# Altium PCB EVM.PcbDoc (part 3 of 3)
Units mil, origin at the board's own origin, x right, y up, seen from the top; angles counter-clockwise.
Board outline 4950 x 3450 mil, 6 copper layers (Top Layer, Power Layer 1 (PWR), Power Layer 2 (GND), Power Layer 3 (PWR), Power Layer 4 (GND), Bottom Layer), stack 58.4 mil thick; 378 components, 191 nets, 2749 pads, 0 vias.
Unrouted connection lines stored in the file: 482.
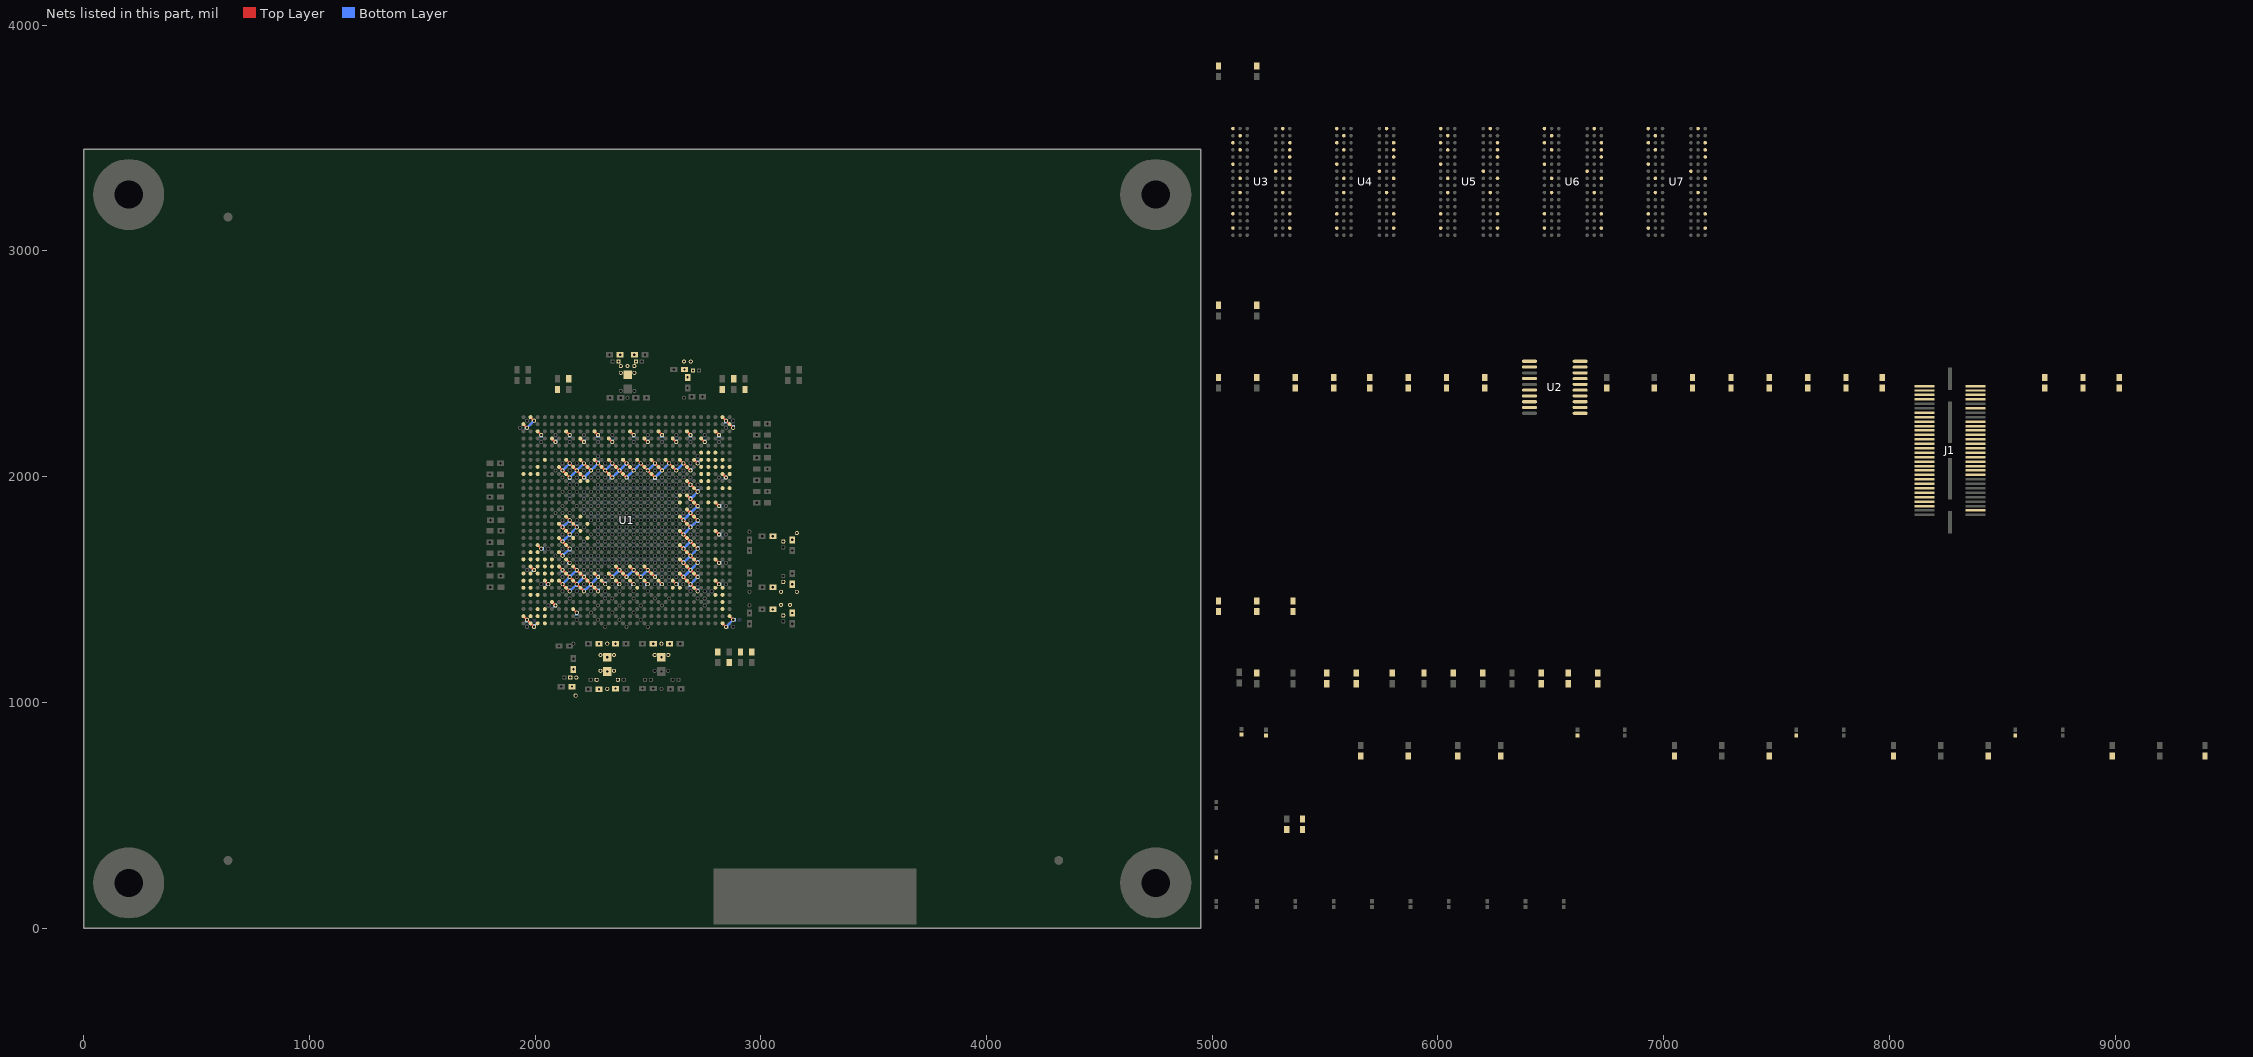
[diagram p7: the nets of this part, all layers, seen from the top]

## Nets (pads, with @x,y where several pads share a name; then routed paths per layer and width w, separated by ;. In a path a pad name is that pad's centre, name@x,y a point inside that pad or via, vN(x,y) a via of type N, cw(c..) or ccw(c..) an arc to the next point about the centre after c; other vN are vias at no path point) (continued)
K2L_DVDD1V5: C188.1 C189.1 C190.1 C191.1 C192.1 C193.1 C194.1 C195.1 C196.1 C197.1 C198.1 C199.1 C200.1 C201.1 C202.1 C203.1 C204.1 C205.1 C206.1 C207.1 C208.1 C209.1 C210.1 C211.1 C212.1 C213.1 C214.1 C215.1 C216.1 C217.1 C218.1 C219.1 C220.1 C221.1 C222.1 C223.1 C224.1 C225.1 C226.1 C227.1 C228.1 C231.1 C232.1 C233.1 C234.1 pad.62@2153.54,1618.11 pad.79@2122.05,2027.56 pad.79@2153.54,1996.06 pad.79@2153.54,2059.06 pad.79@2185.04,2027.56 pad.79@2216.54,1996.06 pad.79@2216.54,2059.06 pad.79@2248.03,2027.56 pad.79@2279.53,2059.06 pad.79@2311.02,2027.56 pad.79@2342.52,1996.06 pad.79@2342.52,2059.06 pad.79@2374.02,2027.56 pad.79@2405.51,1996.06 pad.79@2405.51,2059.06 pad.79@2437.01,2027.56 pad.79@2468.5,2059.06 pad.79@2500,2027.56 pad.79@2531.5,2059.06 pad.79@2562.99,2027.56 pad.79@2594.49,2059.06 pad.79@2625.98,2027.56 pad.79@2657.48,2059.06 pad.79@2688.98,2027.56 pad.79@2720.47,2059.06 pad.98@2531.5,1996.06 pad.100@1964.57,2216.54 pad.100@1996.06,2248.03 pad.100@2027.56,2185.04 pad.100@2090.55,2153.54 pad.100@2153.54,2185.04 pad.100@2216.54,2153.54 pad.100@2279.53,2185.04 pad.100@2342.52,2153.54 pad.100@2437.01,2185.04 pad.100@2500,2153.54 pad.100@2562.99,2185.04 pad.100@2625.98,2153.54 pad.100@2688.98,2185.04 pad.100@2751.97,2153.54 pad.100@2814.96,2185.04 pad.100@2846.46,2248.03 pad.100@2877.95,2216.54 U1.A2 U1.A29 U1.AA7 U1.B1 U1.B30 U1.C3 U1.C7 U1.C11 U1.C16 U1.C20 U1.C24 U1.C28 U1.D5 U1.D9 U1.D13 U1.D18 U1.D22 U1.D26 U1.G7 U1.G9 U1.G11 U1.G13 U1.G15 U1.G17 U1.G19 U1.G21 U1.G23 U1.G25 U1.H6 U1.H8 U1.H10 U1.H12 U1.H14 U1.H16 U1.H18 U1.H20 U1.H22 U1.H24 U1.J7 U1.J9 U1.J13 U1.J15 U1.J19 | length 1959.9
  Top Layer w10: U1.B1@1948.82,2232.28 pad.100@1964.57,2216.54 ; U1.A2@1980.32,2263.78 pad.100@1996.06,2248.03 ; U1.C3@2011.81,2200.79 pad.100@2027.56,2185.04 ; U1.D5@2074.8,2169.29 pad.100@2090.55,2153.54 ; U1.H6@2106.3,2043.31 pad.79@2153.54,1996.06 ; U1.AA7@2137.8,1633.86 pad.62@2153.54,1618.11 ; U1.G7@2137.8,2074.8 pad.79@2153.54,2059.06 U1.H8@2169.29,2043.31 pad.79@2185.04,2027.56 U1.J9@2200.79,2011.81 pad.79@2216.54,1996.06 ; U1.C7@2137.8,2200.79 pad.100@2153.54,2185.04 ; U1.G9@2200.79,2074.8 U1.H10@2232.28,2043.31 pad.79@2248.03,2027.56 ; U1.D9@2200.79,2169.29 pad.100@2216.54,2153.54 ; U1.G11@2263.78,2074.8 U1.H12@2295.28,2043.31 pad.79@2311.02,2027.56 pad.79@2342.52,1996.06 ; U1.C11@2263.78,2200.79 pad.100@2279.53,2185.04 ; U1.G13@2326.77,2074.8 pad.79@2342.52,2059.06 U1.H14@2358.27,2043.31 pad.79@2374.02,2027.56 U1.J15@2389.76,2011.81 pad.79@2405.51,1996.06 ; U1.D13@2326.77,2169.29 pad.100@2342.52,2153.54 ; U1.G15@2389.76,2074.8 pad.79@2405.51,2059.06 pad.79@2437.01,2027.56 ; U1.C16@2421.26,2200.79 pad.100@2437.01,2185.04 ; U1.G17@2452.76,2074.8 U1.H18@2484.25,2043.31 pad.79@2500,2027.56 U1.J19@2515.75,2011.81 pad.98@2531.5,1996.06 ; U1.D18@2484.25,2169.29 pad.100@2500,2153.54 ; U1.G19@2515.75,2074.8 pad.79@2531.5,2059.06 pad.79@2562.99,2027.56 ; U1.C20@2547.24,2200.79 pad.100@2562.99,2185.04 ; U1.G21@2578.74,2074.8 pad.79@2625.98,2027.56 ; U1.D22@2610.24,2169.29 pad.100@2625.98,2153.54 ; U1.G23@2641.73,2074.8 pad.79@2657.48,2059.06 U1.H24@2673.23,2043.31 pad.79@2688.98,2027.56 ; U1.C24@2673.23,2200.79 pad.100@2688.98,2185.04 ; U1.G25@2704.72,2074.8 pad.79@2720.47,2059.06 ; U1.D26@2736.22,2169.29 pad.100@2751.97,2153.54 ; U1.C28@2799.21,2200.79 pad.100@2814.96,2185.04 ; U1.A29@2830.71,2263.78 pad.100@2877.95,2216.54
  Bottom Layer w10: pad.100@1964.57,2216.54 pad.100@1996.06,2248.03 ; pad.79@2122.05,2027.56 pad.79@2153.54,2059.06 ; pad.79@2153.54,1996.06 pad.79@2185.04,2027.56 pad.79@2216.54,2059.06 ; pad.79@2216.54,1996.06 pad.79@2279.53,2059.06 ; pad.79@2311.02,2027.56 pad.79@2342.52,2059.06 ; pad.79@2342.52,1996.06 pad.79@2374.02,2027.56 pad.79@2405.51,2059.06 ; pad.79@2405.51,1996.06 pad.79@2437.01,2027.56 pad.79@2468.5,2059.06 ; pad.79@2500,2027.56 pad.79@2531.5,2059.06 ; pad.98@2531.5,1996.06 pad.79@2594.49,2059.06 ; pad.79@2625.98,2027.56 pad.79@2657.48,2059.06
K2L_DVDD1V8: C132.1 C133.1 C134.1 C135.1 C136.1 C137.1 C138.1 C139.1 C140.1 C141.1 C142.1 C143.1 C144.1 C145.1 C146.1 C147.1 C148.1 C149.1 C150.1 C151.1 C152.1 C153.1 C154.1 C155.1 C156.1 C157.1 C158.1 C159.1 C160.1 C161.1 C162.1 C163.1 C164.1 C165.1 C166.1 C167.1 C168.1 C169.1 C170.1 C171.1 C172.1 C173.1 C174.1 C175.1 C176.1 C177.1 C178.1 C179.1 C180.1 C181.1 C182.1 C183.1 C184.1 C185.1 C186.1 C187.1 C267.1 C273.1 C275.1 C276.1 C278.1 C280.1 C282.1 C289.1 C291.1 C292.1 C294.1 C296.1 C298.1 C300.1 C302.1 C304.1 C306.1 C308.1 C310.1 L6.2 L7.2 L8.2 L9.2 L10.2 L11.2 L12.2 pad.67@1964.57,1366.14 pad.67@1996.06,1334.65 pad.67@1996.06,1586.61 pad.67@2027.56,1681.1 pad.67@2059.06,1523.62 pad.67@2090.55,1429.13 pad.67@2122.05,1523.62 pad.67@2122.05,1586.61 pad.67@2122.05,1649.61 pad.67@2122.05,1712.6 pad.67@2122.05,1775.59 pad.67@2153.54,1492.13 pad.67@2153.54,1555.12 pad.67@2153.54,1681.1 pad.67@2153.54,1744.09 pad.67@2153.54,1807.09 pad.67@2155.98,1110 pad.67@2163.62,1070 pad.67@2170,1146.38 pad.67@2180,1030 pad.67@2182.99,1110 pad.67@2185.04,1397.64 pad.67@2185.04,1523.62 pad.67@2185.04,1586.61 pad.67@2185.04,1775.59 pad.67@2216.54,1492.13 pad.67@2216.54,1555.12 pad.67@2248.03,1523.62 pad.67@2272.99,1100 pad.67@2279.53,1492.13 pad.67@2279.53,1555.12 pad.67@2283.62,1058.5 pad.67@2290,1140 pad.67@2320,1060 pad.67@2320,1137.01 pad.67@2350,1140 pad.67@2356.38,1061.5 pad.67@2367.01,1100 pad.98@2370,2510 pad.98@2377.24,2540 pad.98@2380,2460 pad.98@2380,2490 pad.98@2410,2490 pad.98@2440,2460 pad.98@2440,2490 pad.98@2440,2540 pad.98@2447.01,2510 pad.100@2657.48,1555.12 pad.100@2657.48,1618.11 pad.100@2657.48,1681.1 pad.100@2657.48,1744.09 pad.100@2657.48,1807.09 pad.100@2660,2510 pad.100@2661.89,2474.49 pad.100@2676.06,2440 pad.100@2688.98,1523.62 pad.100@2688.98,1586.61 pad.100@2688.98,1649.61 pad.100@2688.98,1712.6 pad.100@2688.98,1775.59 pad.100@2688.98,1838.58 pad.100@2688.98,1901.57 pad.100@2688.98,1964.57 pad.100@2690,2510 pad.100@2700,2470 pad.100@2720.47,1492.13 pad.100@2720.47,1555.12 pad.100@2720.47,1618.11 pad.100@2720.47,1681.1 pad.100@2720.47,1807.09 pad.100@2720.47,1870.08 pad.100@2720.47,1933.07 pad.100@2814.96,1523.62 pad.100@2814.96,1618.11 pad.100@2814.96,1744.09 pad.100@2814.96,1870.08 pad.100@2846.46,1334.65 pad.100@2846.46,1996.06 pad.100@2877.95,1366.14 pad.100@3053.62,1412 pad.100@3053.62,1510 pad.100@3053.62,1736.38 pad.100@3090,1432 pad.100@3090,1490 pad.100@3100,1384.99 pad.100@3100,1534.02 pad.100@3100,1712.99 pad.100@3130,1432 pad.100@3140,1395.62 pad.100@3140,1523.39 pad.100@3140,1720 pad.100@3160,1490 pad.100@3160,1750 R17.2 R18.2 R19.2 R25.2 U1.AA23 U1.AA25 U1.AA28 U1.AB2 U1.AB6 U1.AB8 U1.AB24 U1.AC7 U1.AC9 U1.AC11 U1.AC23 U1.AC25 U1.AD4 U1.AD6 U1.AD8 U1.AD10 U1.AD24 U1.AD28 U1.AE7 U1.AE9 U1.AE11 U1.AE25 U1.AG5 U1.AH8 U1.AJ1 U1.AJ30 U1.AK2 U1.AK29 U1.J29 U1.K24 U1.L25 U1.M24 U1.N25 U1.N28 U1.P24 U1.R7 U1.R23 U1.R25 U1.T6 U1.T8 U1.T24 U1.U7 U1.U23 U1.U28 U1.V6 U1.V24 U1.W3 U1.W7 U1.W23 U1.W25 U1.Y6 U1.Y24 U2.20 | length 2650.3
  Top Layer w10: U1.AJ1@1948.82,1381.89 pad.67@1964.57,1366.14 pad.67@1996.06,1334.65 ; U1.AB2@1980.32,1602.36 pad.67@1996.06,1586.61 ; U1.W3@2011.81,1696.85 pad.67@2027.56,1681.1 ; U1.AD4@2043.31,1539.37 pad.67@2059.06,1523.62 ; U1.AG5@2074.8,1444.88 pad.67@2090.55,1429.13 ; U1.AD6@2106.3,1539.37 U1.AE7@2137.8,1507.87 pad.67@2153.54,1492.13 ; U1.AB6@2106.3,1602.36 pad.67@2153.54,1555.12 pad.67@2216.54,1492.13 ; U1.Y6@2106.3,1665.35 pad.67@2122.05,1649.61 ; U1.V6@2106.3,1728.35 pad.67@2122.05,1712.6 U1.W7@2137.8,1696.85 pad.67@2153.54,1681.1 ; U1.T6@2106.3,1791.34 U1.U7@2137.8,1759.84 pad.67@2153.54,1744.09 ; U1.R7@2137.8,1822.83 pad.67@2153.54,1807.09 pad.67@2185.04,1775.59 ; U1.AH8@2169.29,1413.39 pad.67@2185.04,1397.64 ; U1.AB8@2169.29,1602.36 U1.AC9@2200.79,1570.87 pad.67@2216.54,1555.12 pad.67@2248.03,1523.62 U1.AE11@2263.78,1507.87 pad.67@2279.53,1492.13 ; U1.AC11@2263.78,1570.87 pad.67@2279.53,1555.12 ; U1.AC23@2641.73,1570.87 pad.100@2657.48,1555.12 U1.AD24@2673.23,1539.37 U1.AE25@2704.72,1507.87 pad.100@2720.47,1492.13 ; U1.AA23@2641.73,1633.86 pad.100@2657.48,1618.11 U1.AB24@2673.23,1602.36 U1.AC25@2704.72,1570.87 pad.100@2720.47,1555.12 ; U1.W23@2641.73,1696.85 pad.100@2657.48,1681.1 U1.Y24@2673.23,1665.35 U1.AA25@2704.72,1633.86 pad.100@2720.47,1618.11 ; U1.U23@2641.73,1759.84 pad.100@2657.48,1744.09 pad.100@2688.98,1712.6 pad.100@2720.47,1681.1 ; U1.R23@2641.73,1822.83 pad.100@2657.48,1807.09 U1.T24@2673.23,1791.34 pad.100@2688.98,1775.59 ; U1.P24@2673.23,1854.33 U1.R25@2704.72,1822.83 pad.100@2720.47,1807.09 ; U1.M24@2673.23,1917.32 U1.N25@2704.72,1885.83 pad.100@2720.47,1870.08 ; U1.K24@2673.23,1980.31 pad.100@2720.47,1933.07 ; U1.AD28@2799.21,1539.37 pad.100@2814.96,1523.62 ; U1.AA28@2799.21,1633.86 pad.100@2814.96,1618.11 ; U1.U28@2799.21,1759.84 pad.100@2814.96,1744.09 ; U1.N28@2799.21,1885.83 pad.100@2814.96,1870.08 ; U1.AK29@2830.71,1350.39 pad.100@2846.46,1334.65 ; U1.J29@2830.71,2011.81 pad.100@2846.46,1996.06 ; U1.AJ30@2862.2,1381.89 pad.100@2877.95,1366.14
  Bottom Layer w10: pad.67@2122.05,1523.62 pad.67@2153.54,1555.12 pad.67@2185.04,1586.61 ; pad.67@2122.05,1649.61 pad.67@2153.54,1681.1 ; pad.67@2122.05,1712.6 pad.67@2153.54,1744.09 pad.67@2185.04,1775.59 ; pad.67@2122.05,1775.59 pad.67@2153.54,1807.09 ; pad.67@2153.54,1492.13 pad.67@2216.54,1555.12 ; pad.67@2216.54,1492.13 pad.67@2248.03,1523.62 pad.67@2279.53,1555.12 ; pad.100@2657.48,1555.12 pad.100@2688.98,1586.61 pad.100@2720.47,1618.11 ; pad.100@2657.48,1618.11 pad.100@2720.47,1681.1 ; pad.100@2657.48,1681.1 pad.100@2688.98,1712.6 ; pad.100@2657.48,1744.09 pad.100@2688.98,1775.59 pad.100@2720.47,1807.09 ; pad.100@2657.48,1807.09 pad.100@2688.98,1838.58 pad.100@2720.47,1870.08 ; pad.100@2688.98,1523.62 pad.100@2720.47,1555.12 ; pad.100@2688.98,1901.57 pad.100@2720.47,1933.07 ; pad.100@2846.46,1334.65 pad.100@2877.95,1366.14
K2L_DVDD3V3: C260.1 C261.1 C262.1 C264.1 C266.1 L5.2 R1.2 R2.2 R3.2 U1.R9
K2L_GPIO00_SPI2SCS1_LENDIAN: R14.1 U1.G26
K2L_GPIO01_SPI2SCS2_BOOTMODE00: U1.F27
K2L_GPIO02_SPI2SCS3_BOOTMODE01: U1.F26
K2L_GPIO03_SPI2SCS4_BOOTMODE02: U1.G29
K2L_GPIO04_TIMI2_BOOTMODE03: U1.F28
K2L_GPIO05_TIMI3_BOOTMODE04: U1.G27
K2L_GPIO06_TIMI4_BOOTMODE05: U1.H30
K2L_GPIO07_TIMI5_BOOTMODE06: U1.J26
K2L_GPIO08_TIMI6_BOOTMODE07: U1.H26
K2L_GPIO09_TIMI6_BOOTMODE08: U1.H29
K2L_GPIO10_TIMO2_BOOTMODE09: U1.J27
K2L_GPIO11_TIMO3_BOOTMODE10: U1.H28
K2L_GPIO12_TIMO3_BOOTMODE10: U1.G28
K2L_GPIO13_TIMO5_BOOTMODE12: U1.H27
K2L_GPIO14_TIMO6_MAINPLLODSEL: U1.J30
K2L_GPIO15_ARMBENDIAN: U1.K27
K2L_GPIO16_CSISC23MUX: U1.K26
K2L_LRESETNMIENZ: R3.1 U1.AF2
K2L_LRESETZ: R1.1 U1.AK3
K2L_MIPI_DETECTZ: J1.58 R25.1
K2L_MIPI_EMU00: J1.19 U1.AC3
K2L_MIPI_EMU01: J1.21 U1.AD5
K2L_MIPI_EMU02: J1.13 U1.AD1
K2L_MIPI_EMU03: J1.17 U1.AD2
K2L_MIPI_EMU04: J1.23 U1.AE1
K2L_MIPI_EMU05: J1.25 U1.AC4
K2L_MIPI_EMU06: J1.27 U1.AC5
K2L_MIPI_EMU07: J1.29 U1.AC2
K2L_MIPI_EMU08: J1.31 U1.AC1
K2L_MIPI_EMU09: J1.33 U1.AB4
K2L_MIPI_EMU10: J1.35 U1.AB5
K2L_MIPI_EMU11: J1.37 U1.AB3
K2L_MIPI_EMU12: J1.39 U1.AA1
K2L_MIPI_EMU13: J1.41 U1.AA4
K2L_MIPI_EMU14: J1.43 U1.AA2
K2L_MIPI_EMU15: J1.45 U1.AA3
K2L_MIPI_EMU16: J1.47 U1.AA5
K2L_MIPI_EMU17: J1.49 U1.Y3
K2L_MIPI_EMU18: J1.51 U1.Y2
K2L_MIPI_EMU19: J1.53
K2L_MIPI_EMU20: J1.55
K2L_MIPI_EMU21: J1.18
K2L_MIPI_EMU22: J1.20
K2L_MIPI_EMU23: J1.22
K2L_MIPI_EMU24: J1.24
K2L_MIPI_EMU25: J1.26
K2L_MIPI_EMU26: J1.28
K2L_MIPI_EMU27: J1.30
K2L_MIPI_EMU28: J1.32
K2L_MIPI_EMU29: J1.34
K2L_MIPI_EMU30: J1.36
K2L_MIPI_EMU31: J1.38
K2L_MIPI_EMU32: J1.40
K2L_MIPI_EMU33: J1.42
K2L_MIPI_TCK: R31.2 U1.AJ3
K2L_MIPI_TCK_BUFF: R21.1 U2.11 U2.13
K2L_MIPI_TCK_BUFF_RS: J1.3 R21.2
K2L_MIPI_TCK_RS: R31.1 U2.9
K2L_MIPI_TCKR_BUFF: J1.7 R32.2
K2L_MIPI_TCKR_BUFF_RS: R32.1 U2.7
K2L_MIPI_TDI: R30.2 U1.AJ4
K2L_MIPI_TDI_BUFF: R22.1 U2.8
K2L_MIPI_TDI_BUFF_RS: J1.5 R22.2
K2L_MIPI_TDI_RS: R30.1 U2.12
K2L_MIPI_TDO: J1.4 R29.2
K2L_MIPI_TDO_BUFF: R24.1 U2.6
K2L_MIPI_TDO_BUFF_RS: R24.2 U1.AH4
K2L_MIPI_TDO_RS: R29.1 U2.14
K2L_MIPI_TGTDETECTZ: J1.15 R26.1
K2L_MIPI_TGTRSTZ: J1.6 R17.1
K2L_MIPI_TMS: R28.2 U1.AH3
K2L_MIPI_TMS_BUFF: R20.2 U2.4
K2L_MIPI_TMS_BUFF_RS: J1.2 R20.1
K2L_MIPI_TMS_RS: R28.1 U2.16
K2L_MIPI_TRSTZ: R27.2 U1.AK4
K2L_MIPI_TRSTZ_BUFF: R23.2 U2.2
K2L_MIPI_TRSTZ_BUFF_RS: J1.8 R23.1
K2L_MIPI_TRSTZ_RS: R27.1 U2.18
K2L_MIPI_VREF_JTAG: J1.1 R18.1
K2L_NMIZ: R2.1 U1.AJ2
K2L_PLLLOCK: R12.2 U1.AH29
K2L_PLLOBSCLKN: U1.AE28
K2L_PLLOBSCLKP: U1.AE29
K2L_PORZ: R6.2 U1.G4
K2L_RESETFULLZ: R7.2 U1.AE2
K2L_RESETSTATZ: R4.2 U1.AE4
K2L_RESETZ: R8.2 U1.AF3
K2L_SPI0CLK_RS: R14.2 U1.L29
K2L_SPI0SCS0: R16.1
K2L_SPI0SCS0_RS: R16.2 U1.L30
K2L_SPI0SIMO: R15.1
K2L_SPI0SIMO_RS: R15.2 U1.L27
K2L_SPI0SOMI: U1.N27
K2L_SYSCLKN: R9.1 U1.AG29
K2L_SYSCLKOUT: R10.2
K2L_SYSCLKOUT_RS: R10.1 U1.AF28
K2L_SYSCLKP: R9.2 U1.AF29
K2L_TIMI0_AVSIFSEL0: U1.J2
K2L_TIMI1_AVSIFSEL1: U1.J1
K2L_TIMO0_CSISC20MUX: U1.H3
K2L_TIMO1_CSISC20CLKCTL: U1.J3
K2L_VDDAHV_1V8_FILT: C283.1 C284.1 C285.1 C286.1 C287.1 C288.1 C290.1 C293.1 L8.1 pad.57@2311.02,1523.62 pad.57@2374.02,1523.62 pad.57@2437.01,1523.62 pad.57@2500,1523.62 pad.57@2562.99,1523.62 pad.57@2625.98,1523.62 pad.67@2283.62,1260 pad.67@2290,1210 pad.67@2320,1200 pad.67@2320,1260 pad.67@2350,1210 pad.67@2356.38,1260 U1.AD12 U1.AD14 U1.AD16 U1.AD18 U1.AD20 U1.AD22 | length 133.6
  Top Layer w10: U1.AD12@2295.28,1539.37 pad.57@2311.02,1523.62 ; U1.AD14@2358.27,1539.37 pad.57@2374.02,1523.62 ; U1.AD16@2421.26,1539.37 pad.57@2437.01,1523.62 ; U1.AD18@2484.25,1539.37 pad.57@2500,1523.62 ; U1.AD20@2547.24,1539.37 pad.57@2562.99,1523.62 ; U1.AD22@2610.24,1539.37 pad.57@2625.98,1523.62
K2L_VDDALV_FILT: C235.1 C236.1 C237.1 C238.1 C239.1 C240.1 C241.1 C242.1 C243.1 L1.1 pad.57@2342.52,1555.12 pad.57@2374.02,1586.61 pad.57@2405.51,1555.12 pad.57@2437.01,1586.61 pad.57@2468.5,1555.12 pad.57@2500,1586.61 pad.57@2531.5,1555.12 pad.67@2523.62,1260 pad.67@2530,1210 pad.67@2560,1200 pad.67@2560,1260 pad.67@2590.55,1210.16 pad.67@2596.38,1260 U1.AB14 U1.AB16 U1.AB18 U1.AC13 U1.AC15 U1.AC17 U1.AC19 | length 356.3
  Top Layer w10: U1.AC13@2326.77,1570.87 pad.57@2342.52,1555.12 ; U1.AB14@2358.27,1602.36 pad.57@2405.51,1555.12 ; U1.AB16@2421.26,1602.36 pad.57@2468.5,1555.12 ; U1.AB18@2484.25,1602.36 pad.57@2531.5,1555.12
  Bottom Layer w10: pad.57@2342.52,1555.12 pad.57@2374.02,1586.61 ; pad.57@2405.51,1555.12 pad.57@2437.01,1586.61 ; pad.57@2468.5,1555.12 pad.57@2500,1586.61
K2L_VDDCMON: U1.K10
K2L_VDDTMON: U1.N23
K2L_VDDUSB: C256.1 C258.1 L4.1 U1.U9
K2L_VP_FILT: C248.1 C250.1 L2.1 U1.V8
K2L_VPH_FILT: C263.1 C265.1 L5.1 U1.T10
K2L_VPTX_FILT: C252.1 C254.1 L3.1 U1.V10
K2L_VSSCMON: U1.K9
K2L_VSSTMON: U1.M23
MIPI_VREF_EMU: J1.12 R19.1
NetR33_2: R33.2 U2.15 U2.17
NetR34_2: R34.2 U2.1 U2.19
NetR35_2: R35.2 U1.AE17
NetR36_2: R36.2 U1.AE13
NetR37_2: R37.2 U1.AE22
NetR38_2: R38.2 U1.AE23
NetU3_A1: U3.A1 U3.A8 U3.C1 U3.C9 U3.D2 U3.E9 U3.F1 U3.H2 U3.H9
NetU3_B2: U3.B2 U3.D9 U3.G7 U3.K2 U3.K8 U3.N1 U3.N9 U3.R1 U3.R9
NetU4_A1: U4.A1 U4.A8 U4.C1 U4.C9 U4.D2 U4.E9 U4.F1 U4.H2 U4.H9
NetU4_B2: U4.B2 U4.D9 U4.G7 U4.K2 U4.K8 U4.N1 U4.N9 U4.R1 U4.R9
NetU5_A1: U5.A1 U5.A8 U5.C1 U5.C9 U5.D2 U5.E9 U5.F1 U5.H2 U5.H9
NetU5_B2: U5.B2 U5.D9 U5.G7 U5.K2 U5.K8 U5.N1 U5.N9 U5.R1 U5.R9
NetU6_A1: U6.A1 U6.A8 U6.C1 U6.C9 U6.D2 U6.E9 U6.F1 U6.H2 U6.H9
NetU6_B2: U6.B2 U6.D9 U6.G7 U6.K2 U6.K8 U6.N1 U6.N9 U6.R1 U6.R9
NetU7_A1: U7.A1 U7.A8 U7.C1 U7.C9 U7.D2 U7.E9 U7.F1 U7.H2 U7.H9
NetU7_B2: U7.B2 U7.D9 U7.G7 U7.K2 U7.K8 U7.N1 U7.N9 U7.R1 U7.R9
pads on no net: FID1.1 FID2.1 FID3.1 H1.1 H2.1 H3.1 H4.1 H9.0 H10.0 H11.0 H12.0 J1.9 J1.10 J1.11 J1.14 J1.44 J1.46 J1.48 J1.50 J1.52 J1.54 J1.56 J1.59 J1.60 J1.MH1 J1.MH2 Logo1.0 U1.A3 U1.A4 U1.A5 U1.A6 U1.A7 U1.A8 U1.A9 U1.A10 U1.A11 U1.A12 U1.A13 U1.A14 U1.A15 U1.A16 U1.A17 U1.A18 U1.A19 U1.A20 U1.A21 U1.A22 U1.A23 U1.A24 U1.A25 U1.A26 U1.A27 U1.A28 U1.AA26 U1.AA27 U1.AA30 U1.AB26 U1.AB27 U1.AB28 U1.AB29 U1.AB30 U1.AC26 U1.AC27 U1.AC28 U1.AC29 U1.AC30 U1.AD26 U1.AD27 U1.AD30 U1.AE3 U1.AE15 U1.AE21 U1.AE30 U1.AF1 U1.AF4 U1.AF5 U1.AF6 U1.AF8 U1.AF9 U1.AF10 U1.AF11 U1.AF20 U1.AF22 U1.AF30 U1.AG1 U1.AG2 U1.AG7 U1.AG8 U1.AG9 U1.AG10 U1.AG12 U1.AG13 U1.AG27 U1.AH1 U1.AH2 U1.AH5 U1.AH7 U1.AH9 U1.AH11 U1.AH12 U1.AH26 U1.AH27 U1.AH28 U1.AJ5 U1.AJ6 U1.AJ7 U1.AJ9 U1.AJ10 U1.AJ12 U1.AJ13 U1.AJ27 U1.AJ28 U1.AJ29 U1.AK5 U1.AK6 U1.AK7 U1.AK8 U1.AK9 U1.AK10 U1.AK11 U1.AK13 U1.AK14 U1.AK28 U1.B2 U1.B3 U1.B4 U1.B5 U1.B6 U1.B7 U1.B8 U1.B9 U1.B10 U1.B11 U1.B12 U1.B13 U1.B14 U1.B15 U1.B16 U1.B17 U1.B18 U1.B19 U1.B20 U1.B21 U1.B22 U1.B23 U1.B24 U1.B25 U1.B26 U1.B27 U1.B28 U1.B29 U1.C1 U1.C2 U1.C4 U1.C6 U1.C8 U1.C10 U1.C12 U1.C14 U1.C15 U1.C17 U1.C19 U1.C21 U1.C23 U1.C25 U1.C27 U1.C29 U1.C30 U1.D1 U1.D2 U1.D4 U1.D6 U1.D8 U1.D10 U1.D12 U1.D14 U1.D15 U1.D17 U1.D19 U1.D21 U1.D23 U1.D25 U1.D27 U1.D29 U1.D30 U1.E1 U1.E2 U1.E3 U1.E4 U1.E5 U1.E6 U1.E7 U1.E8 U1.E9 U1.E10 U1.E11 U1.E12 U1.E13 U1.E14 U1.E15 U1.E16 U1.E17 U1.E18 U1.E19 U1.E20 U1.E21 U1.E22 U1.E23 U1.E24 U1.E25 U1.E26 U1.E27 U1.E28 U1.E29 U1.E30 U1.F1 U1.F2 U1.F3 U1.F5 U1.F6 U1.F7 U1.F8 U1.F9 U1.F10 U1.F11 U1.F12 U1.F13 U1.F14 U1.F15 U1.F17 U1.F18 U1.F19 U1.F20 U1.F21 U1.F22 U1.F23 U1.F24 U1.F25 U1.F29 U1.G2 U1.H1 U1.H25 U1.J4 U1.J5 U1.J25 U1.K2 U1.K3 U1.K4 U1.K5 U1.K28 U1.K29 U1.K30 U1.L1 U1.L3 U1.L4 U1.L5 U1.L26 U1.L28 U1.M1 U1.M2 U1.M3 U1.M4 U1.M5 U1.M6 U1.M8 U1.M26 U1.M27 U1.M28 U1.M29 U1.M30 U1.N2 U1.N4 U1.N5 U1.N26 U1.N30 U1.P1 U1.P3 U1.P26 U1.P27 U1.P28 U1.P29 U1.P30 U1.R1 U1.R2 U1.R3 U1.R26 U1.R27 U1.R28 U1.R29 U1.R30 U1.T2 U1.T3 U1.T4 U1.T5 U1.T26 U1.T27 U1.T28 U1.T29 U1.T30 U1.U1 U1.U3 U1.U4 U1.U5 U1.U26 U1.U27 U1.U30 U1.V1 U1.V2 U1.V3 U1.V4 U1.V5 U1.V26 U1.V27 U1.V28 U1.V29 U1.V30 U1.W1 U1.W2 U1.W5 U1.W26 U1.W27 U1.W28 U1.W29 U1.W30 U1.Y1 U1.Y4 U1.Y26 U1.Y27 U1.Y28 U1.Y29 U1.Y30 U2.3 U2.5 U3.A2 U3.A3 U3.A7 U3.B7 U3.B8 U3.C2 U3.C3 U3.C7 U3.C8 U3.D3 U3.D7 U3.E3 U3.E7 U3.F2 U3.F3 U3.F7 U3.F8 U3.G2 U3.G3 U3.H1 U3.H3 U3.H7 U3.H8 U3.J1 U3.J3 U3.J7 U3.J9 U3.K1 U3.K3 U3.K7 U3.K9 U3.L1 U3.L2 U3.L3 U3.L7 U3.L8 U3.L9 U3.M2 U3.M3 U3.M7 U3.M8 U3.N2 U3.N3 U3.N7 U3.N8 U3.P2 U3.P3 U3.P7 U3.P8 U3.R2 U3.R3 U3.R7 U3.R8 U3.T2 U3.T3 U3.T7 U3.T8 U4.A2 U4.A3 U4.A7 U4.B7 U4.B8 U4.C2 U4.C3 U4.C7 U4.C8 U4.D3 U4.D7 U4.E3 U4.E7 U4.F2 U4.F3 U4.F7 U4.F8 U4.G2 U4.G3 U4.H1 U4.H3 U4.H7 U4.H8 U4.J1 U4.J3 U4.J7 U4.J9 U4.K1 U4.K3 U4.K7 U4.K9 U4.L1 U4.L2 U4.L3 U4.L7 U4.L8 U4.L9 U4.M2 U4.M3 U4.M7 U4.M8 U4.N2 U4.N3 U4.N7 U4.N8 U4.P2 U4.P3 U4.P7 U4.P8 U4.R2 U4.R3 U4.R7 U4.R8 U4.T2 U4.T3 U4.T7 U4.T8 U5.A2 U5.A3 U5.A7 U5.B7 U5.B8 U5.C2 U5.C3 U5.C7 U5.C8 U5.D3 U5.D7 U5.E3 U5.E7 U5.F2 U5.F3 U5.F7 U5.F8 U5.G2 U5.G3 U5.H1 U5.H3 U5.H7 U5.H8 U5.J1 U5.J3 U5.J7 U5.J9 U5.K1 U5.K3 U5.K7 U5.K9 U5.L1 U5.L2 U5.L3 U5.L7 U5.L8 U5.L9 U5.M2 U5.M3 U5.M7 U5.M8 U5.N2 U5.N3 U5.N7 U5.N8 U5.P2 U5.P3 U5.P7 U5.P8 U5.R2 U5.R3 U5.R7 U5.R8 U5.T2 U5.T3 U5.T7 U5.T8 U6.A2 U6.A3 U6.A7 U6.B7 U6.B8 U6.C2 U6.C3 U6.C7 U6.C8 U6.D3 U6.D7 U6.E3 U6.E7 U6.F2 U6.F3 U6.F7 U6.F8 U6.G2 U6.G3 U6.H1 U6.H3 U6.H7 U6.H8 U6.J1 U6.J3 U6.J7 U6.J9 U6.K1 U6.K3 U6.K7 U6.K9 U6.L1 U6.L2 U6.L3 U6.L7 U6.L8 U6.L9 U6.M2 U6.M3 U6.M7 U6.M8 U6.N2 U6.N3 U6.N7 U6.N8 U6.P2 U6.P3 U6.P7 U6.P8 U6.R2 U6.R3 U6.R7 U6.R8 U6.T2 U6.T3 U6.T7 U6.T8 U7.A2 U7.A3 U7.A7 U7.B7 U7.B8 U7.C2 U7.C3 U7.C7 U7.C8 U7.D3 U7.D7 U7.E3 U7.E7 U7.F2 U7.F3 U7.F7 U7.F8 U7.G2 U7.G3 U7.H1 U7.H3 U7.H7 U7.H8 U7.J1 U7.J3 U7.J7 U7.J9 U7.K1 U7.K3 U7.K7 U7.K9 U7.L1 U7.L2 U7.L3 U7.L7 U7.L8 U7.L9 U7.M2 U7.M3 U7.M7 U7.M8 U7.N2 U7.N3 U7.N7 U7.N8 U7.P2 U7.P3 U7.P7 U7.P8 U7.R2 U7.R3 U7.R7 U7.R8 U7.T2 U7.T3 U7.T7 U7.T8

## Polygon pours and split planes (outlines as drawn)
GND on Power Layer 2 (GND) "Power Layer 2-No Net" (solid, remove dead copper, pour order 32): 1600,2700 3300,2700 3300,890 3290,900 1600,900
K2L_VDDALV_FILT on Power Layer 1 (PWR) "Power Layer 1-K2L_VDDALV_FILT_1" (solid, remove dead copper, pour order 33): 2326.77,1555.12 2326.77,1598.42 2330.71,1602.36 2602.36,1602.36 2610,1594.73 2610,1200 2590,1180 2530,1180 2510,1200 2510,1446.69 2448.82,1507.87 2332.14,1507.87 2326.77,1513.24 2326.77,1570.87
K2L_DVDD0V85 on Power Layer 1 (PWR) "Power Layer 1-No Net" (solid, remove dead copper, pour order 36): 2510.09,1159.91 2610.09,1159.91 2640.09,1159.91 2660.09,1139.91 2660.09,800 2460.09,800 2460.09,1139.91 2480.09,1159.91
K2L_DVDD1V8 on Power Layer 1 (PWR) "Power Layer 1 (PWR)-No Net" (solid, remove dead copper, pour order 39): 2390,1160 2100,1160 2080,1140 2080,800 2420,800 2420,1130
K2L_AVDDA1_1V8_FILT on Power Layer 1 (PWR) "Power Layer 1 (PWR)-No Net 2" (solid, remove dead copper, pour order 47): 2641.73,1980.32 2712.6,1980.32 2712.6,2401.57 2704.72,2409.45 2649.61,2409.45 2641.73,2401.57
K2L_AVDDA10_6_1V8_FILT on Power Layer 1 (PWR) "Power Layer 3 (PWR)-No Net" (solid, remove dead copper, pour order 48): 2610.24,2212.6 2610.24,1956.69 2602.36,1948.82 2216.54,1948.82 2177.17,1948.82 2169.29,1956.69 2169.29,2212.6 2177.16,2220.47 2330.71,2220.47 2354.33,2244.09 2354.33,2401.57 2366.14,2413.39 2452.76,2413.39 2464.57,2401.58 2464.57,2236.22 2480.31,2220.47 2602.36,2220.47
K2L_DVDD1V8 on Power Layer 1 (PWR) "Power Layer 1 (PWR)-No Net 3" (solid, remove dead copper, pour order 49): 2310,2440 2740,2440 2750,2450 2750,2800 2300,2800 2300,2450
K2L_AVDDA5_1V8_FILT on Power Layer 1 (PWR) "Power Layer 1 (PWR)-No Net 4" (solid, remove dead copper, pour order 56): 2740.16,1472.44 2803.15,1472.44 2834.65,1440.94 3020,1440.94 3020,1377.95 2779.53,1377.95 2736.22,1421.26 2736.22,1468.5
K2L_AVDDA4_1V8_FILT on Power Layer 1 (PWR) "Power Layer 1 (PWR)-No Net 5" (solid, remove dead copper, pour order 57): 3020,1480.31 2740.16,1480.31 2736.22,1484.25 2736.22,1507.87 2740.16,1511.81 2771.65,1543.31 3020,1543.31
K2L_AVDDA2_1V8_FILT on Power Layer 1 (PWR) "Power Layer 1 (PWR)-No Net 6" (solid, remove dead copper, pour order 58): 2677.17,1791.34 2874.02,1791.34 2893.7,1771.65 3019.96,1771.65 3020.18,1708.66 2894.33,1708.66 2874.02,1696.85 2677.17,1696.85 2673.23,1700.79 2673.23,1787.4
K2L_AVDDA3_1V8_FILT on Power Layer 1 (PWR) "Power Layer 1 (PWR)-No Net 7" (solid, remove dead copper, pour order 59): 2342.52,1504.97 2342.52,1433.07 2338.58,1429.13 2232.28,1429.13 2204.72,1401.57 2204.72,1194.72 2190,1180 2150,1180 2137.8,1192.2 2137.8,1503.94 2141.73,1507.87 2339.62,1507.87
K2L_DVDD1V8 on Power Layer 1 (PWR) "Power Layer 1 (PWR)-No Net 8" (solid, remove dead copper, pour order 60): 3040,1810 3400,1810 3400,1290 3040,1290
K2L_VDDALV_FILT on Top Layer "Top Layer-No Net" (solid, remove dead copper, pour order 34): 2610,1200 2610,1270 2510,1270 2510,1200 2520,1190 2600,1190
K2L_DVDD0V85 on Top Layer "Top Layer-No Net 1" (solid, remove dead copper, pour order 35): 2520,1150 2600,1150 2610,1140 2610,1110 2610,1020 2510,1020 2510,1140
K2L_DVDD1V8 on Top Layer "Top Layer-No Net 2" (solid, remove dead copper, pour order 37): 2280,1150 2360,1150 2370,1140 2370,1020 2270,1020 2270,1140
K2L_VDDAHV_1V8_FILT on Top Layer "Top Layer-No Net 3" (solid, remove dead copper, pour order 38): 2370,1200 2370,1270 2270,1270 2270,1200 2280,1190 2360,1190
K2L_DVDD1V8 on Top Layer "Top Layer-No Net 4" (solid, remove dead copper, pour order 41): 2190,1150 2160,1150 2150,1140 2150,1020 2200,1020 2200,1140
K2L_AVDDA3_1V8_FILT on Top Layer "Top Layer-No Net 5" (solid, remove dead copper, pour order 42): 2200,1190 2200,1270 2140,1270 2140,1190 2150,1180 2190,1180
K2L_DVDD1V8 on Top Layer "Top Layer-No Net 6" (solid, remove dead copper, pour order 43): 2698.27,2434.49 2658.27,2434.49 2648.27,2444.49 2648.27,2530 2708.27,2530 2708.27,2444.49
K2L_AVDDA1_1V8_FILT on Top Layer "Top Layer-No Net 7" (solid, remove dead copper, pour order 44): 2654.49,2404.49 2698.19,2404.49 2710,2392.68 2710,2330 2640,2330 2640,2390
K2L_DVDD1V8 on Top Layer "Top Layer-No Net 8" (solid, remove dead copper, pour order 45): 2450,2450 2450,2570 2370,2570 2370,2450 2380,2440 2440,2440
K2L_AVDDA10_6_1V8_FILT on Top Layer "Top Layer-No Net 9" (solid, remove dead copper, pour order 46): 2450,2400 2370,2400 2360,2390 2360,2330 2460,2330 2460,2390
K2L_AVDDA5_1V8_FILT on Top Layer "Top Layer-No Net 10" (solid, remove dead copper, pour order 50): 3020,1432 3020,1392 3010,1382 2940,1382 2930,1392 2930,1432 2940,1442 3010,1442
K2L_AVDDA4_1V8_FILT on Top Layer "Top Layer-No Net 11" (solid, remove dead copper, pour order 51): 3020,1490 3020,1530 3010,1540 2940,1540 2930,1530 2930,1490 2940,1480 3010,1480
K2L_DVDD1V8 on Top Layer "Top Layer-No Net 12" (solid, remove dead copper, pour order 52): 3040,1530 3040,1490 3050,1480 3180,1480 3180,1540 3050,1540
K2L_DVDD1V8 on Top Layer "Top Layer-No Net 13" (solid, remove dead copper, pour order 53): 3050,1442 3180,1442 3180,1382 3050,1382 3040,1392 3040,1432
K2L_DVDD1V8 on Top Layer "Top Layer-No Net 14" (solid, remove dead copper, pour order 54): 3040,1756.38 3040,1716.38 3050,1706.38 3180,1706.38 3180,1766.38 3050,1766.38
K2L_AVDDA2_1V8_FILT on Top Layer "Top Layer-No Net 15" (solid, remove dead copper, pour order 55): 3020,1716.38 3020,1756.38 3010,1766.38 2940,1766.38 2930,1756.38 2930,1716.38 2940,1706.38 3010,1706.38
GND on Power Layer 4 (GND) "Power Layer 2-No Net" (solid, remove dead copper, pour order 31): 1600,2700 3300,2700 3300,890 3290,900 1600,900
K2L_VDDAHV_1V8_FILT on Power Layer 3 (PWR) "Power Layer 1 (PWR)-No Net 1" (solid, remove dead copper, pour order 40): 2641.73,1484.25 2641.73,1562.99 2633.86,1570.87 2271.65,1570.87 2263.78,1562.99 2263.78,1196.22 2270,1190 2360,1190 2370.08,1200.08 2370.08,1396.85 2432.86,1476.38 2633.86,1476.38

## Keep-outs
Keep-Out Layer:
  lines w10: -5,0 ccw(c0,0) 0,-5 ; -5,0 ccw(c0,0) 0,-5 ; -5,0 -5,3450 ; -5,3450 cw(c0,3450) 0,3455 ; -5,3450 cw(c0,3450) 0,3455 ; 0,-5 4950,-5 ; 0,3455 4950,3455 ; 4950,-5 ccw(c4950,0) 4955,0 ; 4950,-5 ccw(c4950,0) 4955,0 ; 4950,3455 cw(c4950,3450) 4955,3450 ; 4950,3455 cw(c4950,3450) 4955,3450 ; 4955,0 4955,3450
  text ".Layer_Name" at 577,-858.49 h60

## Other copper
Top Layer:
  text ".CopyrightYear" at 532,90 h60
  text "TI" at 808,90 h60
  text "©" at 415,86.48 h105
  text ".Layer_Name" at 577,-858.49 h60
Bottom Layer:
  text ".VersionControl_RevNumber" at 3891,179.5 h60
  text "SVN:" at 4170,179.5 h60
  text "MADE IN U.S." at 1250,86.5 h60
  text "UL94V-0" at 2529.5,86.5 h60
  text ".Layer_Name" at 577,-858.49 h60

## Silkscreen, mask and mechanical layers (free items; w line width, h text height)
Top Overlay:
  region: 2680,210 2380,210 2380,110 2680,110
  lines w10: 2030,910 2030,1010 2080,1050 ; 2320,1010 2360,970 2360,910 ; 2340,2700 2340,2680 2400,2620 ; 2610,2700 2610,2670 2670,2610 ; 2670,1070 2730,1010 2730,960 2730,910 ; 3170,1430 3200,1460 3230,1460 ; 3180,1790 3210,1820 3240,1820 ; 1870,710 1870,910 2060,910 2060,710 1870,710 ; 2100,2700 2470,2700 2470,2880 2100,2880 2100,2700 ; 2140,710 2140,910 2490,910 2490,710 2140,710 ; 2550,710 2900,710 2900,910 2550,910 2550,710 ; 2590,2700 2590,2880 2780,2880 2780,2700 2590,2700 ; 3240,1250 3430,1250 3430,1600 3240,1600 3240,1250 ; 3240,1670 3240,1860 3430,1860 3430,1670 3240,1670
  text ".PRJ_Number" at 1820,130.01 h60
  text ".PCB_Rev" at 2200,130.01 h60
  text "-" at 2310,130.01 h60
  text ".Layer_Name" at 577,-858.49 h60
Bottom Overlay:
  text ".Layer_Name" at 577,-858.49 h60
Top Paste:
  text ".Layer_Name" at 577,-858.49 h60
Bottom Paste:
  text ".Layer_Name" at 577,-858.49 h60
Top Solder:
  text ".Layer_Name" at 577,-858.49 h60
  text ".Layer_Name" at 577,-858.49 h60
Bottom Solder:
  text ".Layer_Name" at 577,-858.49 h60
Drill Guide:
  text ".Layer_Name" at 577,-858.49 h60
M1 Board Outline:
  the board outline again, w10
  text ".Layer_Name" at 577,-858.49 h60
M2 Board Dimensions:
  rectangle: 125,-400 500,-275
  rectangle: 0,-275 125,-150
  lines w7: 0,-275 1000,-275 ; 125,-400 125,-150 ; 250,-400 250,-150 ; 500,-400 500,-150 ; 750,-400 750,-150 ; 0,-400 0,-150 1000,-150 1000,-400 0,-400
  text ".Layer_Name" at 577,-858.49 h60
M3 3D STEP Top:
  text ".Layer_Name" at 577,-858.49 h60
M4 3D STEP Bottom:
  text ".Layer_Name" at 577,-858.49 h60
M5 Assembly Top:
  lines w10: -292,-930.17 6308,-930.17 ; -292,-726.83 6310,-726.83 ; -292,-523.5 -292,-1133.5 3713,-1133.5 6310,-1133.5 6310,-523.5 -291.5,-523.5 -291.5,-1133.5 1284,-1133.5 ; 2173,-1133.5 2173,-523.5 ; 3440,-726.83 3440,-523.5 ; 4280,-726.83 4280,-523.5 ; 4902,-1140 4902,-937.17
  text "COMPONENTS MARKED 'DNP' SHOULD NOT BE POPULATED." at 1153.5,-318.5 h60
  text "ASSEMBLY VARIANT:" at 1153,-434 h60
  text ".VariantName" at 2189,-434 h60
  text "PCB VIEWED FROM TOP SIDE" at -228.5,-655.67 h60
  text "BOARD #:" at 2248,-655.67 h60
  text ".PRJ_Number" at 2793.5,-655.67 h60
  text "REV:" at 3638,-655.67 h60
  text ".PCB_Rev" at 3929.5,-655.67 h60
  text "SVN REV:" at 4476,-655.67 h60
  text ".VersionControl_RevNumber" at 4982,-655.67 h60
  text "PLOT NAME =" at -228.5,-1064.34 h60
  text ".plot_File_Name" at 577,-1064.34 h60
  text "GENERATED    :" at 2250,-1064.34 h60
  text ".Print_Date" at 3119.5,-1064.34 h60
  text ".Print_Time" at 3848.5,-1064.34 h60
  text "TEXAS INSTRUMENTS" at 5113,-1064.34 h60
M6 Assembly Bottom:
  lines w10: -292.5,-727.33 6309.5,-727.33 ; -290.5,-930.67 6309.5,-930.67 ; 1115.5,-1140.5 1115.5,-937.67 ; 1737.5,-727.33 1737.5,-524 ; 2577.5,-727.33 2577.5,-524 ; 3844.5,-1134 3844.5,-524 ; 4733.5,-1134 6309,-1134 6309,-524 -292.5,-524 -292.5,-1134 2304.5,-1134 6309.5,-1134 6309.5,-524
  text "COMPONENTS MARKED 'DNP' SHOULD NOT BE POPULATED." at 6102,-318 h60
  text ".VariantName" at 5058,-434 h60
  text "ASSEMBLY VARIANT:" at 6097,-434 h60
  text ".VersionControl_RevNumber" at 1035.5,-656.17 h60
  text "SVN REV:" at 1541.5,-656.17 h60
  text ".PCB_Rev" at 2088,-656.17 h60
  text "REV:" at 2379.5,-656.17 h60
  text ".PRJ_Number" at 3224,-656.17 h60
  text "BOARD #:" at 3769.5,-656.17 h60
  text "PCB VIEWED FROM BOTTOM SIDE" at 6246,-656.17 h60
  text "TEXAS INSTRUMENTS" at 904.5,-1064.84 h60
  text ".Print_Time" at 2169,-1064.84 h60
  text ".Print_Date" at 2898,-1064.84 h60
  text "GENERATED    :" at 3767.5,-1064.84 h60
  text ".plot_File_Name" at 5440.5,-1064.84 h60
  text "PLOT NAME =" at 6246,-1064.84 h60
M9 Title Sheet:
  drawing of 57 lines, arcs and shapes, not listed
  text "1" at 739.84,8036.5 h70
  text "2" at 3235.5,8036.5 h70
  text "3" at 5724.84,8036.5 h70
  text "4" at 8231.51,8036.5 h70
  text "5" at 10730.5,8036.5 h70
  text "6" at 13235.5,8036.5 h70
  text "A" at -416.5,6893.5 h70
  text "A" at 14383.5,6893.5 h70
  text "B" at -416.5,4513.5 h70
  text "B" at 14383.5,4513.5 h70
  text "C" at -416.5,2138.5 h70
  text "C" at 14383.5,2138.5 h70
  text "PROJECT TITLE:" at 11343.5,277.5 h45
  text ".PRJ_Title" at 11393.5,144.17 h70
  text "DESIGNED FOR:" at 11343.5,-23.5 h45
  text ".PRJ_Customer" at 11393.5,-163.5 h70
  text "D" at -416.5,-231.5 h70
  text "D" at 14383.5,-231.5 h70
  text "FILE NAME:" at 11343.5,-323.5 h45
  text ".PCB_File_Name_No_Path" at 11393.5,-443.5 h70
  text "Texas Instruments (TI) and/or its licensors do not warrant the accuracy or completeness of this specification" at 6374,-605.34 h45
  text "ENGINEER:" at 11343.5,-613.5 h45
  text "LAYOUT BY:" at 12848.5,-613.5 h45
  text "or any information contained therein. TI and/or its licensors do not warrant that this design will meet" at 6329.01,-718 h45
  text ".PRJ_Engineer" at 11393.5,-768.49 h70
  text ".PCB_Layout" at 12899,-768.49 h70
  text "the specifications, will be suitable for your application or fit for any particular purpose, or will operate in" at 6329.01,-830.67 h45
  text ".Layer_Name" at 577,-858.49 h60
  text "ALTIUM DESIGNER VERSION:" at 12848.5,-923.5 h45
  text "an implementation. TI and/or its licensors do not warrant that the design is production worthy. You should" at 6329.01,-943.33 h45
  text "completely validate and test your design implementation to confirm the system functionality for your application." at 6374,-1056 h45
  text ".print_Scale" at 11393.5,-1056.83 h70
  text ".Application_BuildNumber" at 12899,-1056.83 h70
  text "1" at 739.84,-1263.5 h70
  text "2" at 3235.5,-1263.5 h70
  text "3" at 5724.84,-1263.5 h70
  text "4" at 8231.51,-1263.5 h70
  text "5" at 10730.5,-1263.5 h70
  text "6" at 13235.5,-1263.5 h70
M10 Fab Notes:
  drawing of 185 lines, arcs and shapes, not listed
  text "DESIGN INFORMATION" at 12381.02,5910 h60
  text "MIN. TRACK WIDTH:" at 11736.46,5730 h60
  text "8" at 12832.7,5730 h60
  text "MIL" at 12987.46,5730 h60
  text "MIN. CLEARANCE:" at 11736.46,5598 h60
  text "0.2" at 12772.7,5598 h60
  text "mm" at 12987.46,5598 h60
  text "MIN. VIA PAD SIZE:" at 11736.46,5466 h60
  text "24" at 12802.71,5466 h60
  text "MIL" at 12987.46,5466 h60
  text "0.05mm (2MIL)" at 12431.46,5324.29 h60
  text "MINIMUM ANNULAR RING" at 11407.23,5320 h60
  text "EXTERNAL" at 13139.46,5320 h60
  text "PER" at 11607.23,5202 h60
  text "IPC-D-275 CLASS 2 LEVEL C" at 11827.23,5202 h60
  text "MIL, HOLES" at 13315.46,5089.71 h60
  text "+/-" at 12923,5089 h60
  text "+/-" at 13777,5089 h60
  text "REGISTRATION TOLERANCES:" at 11407.23,5084 h60
  text "METAL" at 12607,5084 h60
  text "5" at 13183.2,5084 h60
  text "3" at 14016.2,5084 h60
  text "MIL" at 14132.46,5084 h60
  text "MATERIAL:" at 11332.46,4874.54 h60
  text "FR-4 High Tg" at 12318.9,4734.21 h60
  text "FR-408" at 11753.46,4725.64 h60
  text "X" at 12165.46,4725.64 h60
  text "OTHER" at 13241.46,4725.64 h60
  text "62 MIL (1.6mm) +/-10%" at 12073.56,4562.92 h60
  text "THICKNESS:" at 11407.23,4558.64 h60
  text "X" at 11945.4,4558.64 h60
  text "OTHER" at 13358.46,4558.64 h60
  text "TOLERANCE:" at 11407.23,4400.64 h60
  text "X" at 12246.53,4400.64 h60
  text "ANSI IPC-6012 TYPE 3 CLASS 2" at 12433.48,4400.64 h60
  text "OTHER +/-" at 12433.46,4244.64 h60
  text "BOW & TWIST:" at 11407.23,4087.64 h60
  text "X" at 12246.53,4087.64 h60
  text "ANSI IPC-6012 TYPE 3 CLASS 2" at 12433.48,4087.64 h60
  text "OTHER +/-" at 12433.46,3929.13 h60
  text "DRILLING:" at 11332.46,3790.64 h60
  text "REFERENCE:" at 11407.23,3673.64 h60
  text "X" at 12055.46,3673.64 h60
  text "AS SHOWN" at 12242.46,3673.64 h60
  text "X" at 12956.46,3673.64 h60
  text "NC_DRILL FILES" at 13093.46,3673.64 h60
  text "PTH MIN COPPER THICKNESS:" at 11407.23,3515.64 h60
  text "X" at 12757.46,3515.64 h60
  text "1MIL" at 12894.46,3515.64 h60
  text "OTHER" at 13391.46,3515.64 h60
  text "BOARD FINISH:" at 11332.46,3356.64 h60
  text "SILKSCREEN:" at 11487.68,3238.64 h60
  text "X" at 12436.46,3238.64 h60
  text "TOP" at 12562.46,3238.64 h60
  text "X" at 12946.46,3238.64 h60
  text "BOTTOM" at 13073.46,3238.64 h60
  text "SILKSCREEN COLOR:" at 11487.68,3071.64 h60
  text "X" at 12435.42,3071.64 h60
  text "WHITE" at 12562.46,3071.64 h60
  text "OTHER" at 13073.46,3071.64 h60
  text "SOLDER RESIST COLOR:" at 11487.68,2901.64 h60
  text "X" at 12055.42,2742.44 h60
  text "GREEN" at 12182.46,2742.44 h60
  text "BLUE" at 12773.46,2742.44 h60
  text "OTHER" at 13311.46,2742.44 h60
  text "IMMERSION GOLD (ENIG)" at 12393.46,2553.92 h60
  text "ENEPIG" at 13731,2550.64 h60
  text "SURFACE FINISH:" at 11332.46,2549.64 h60
  text "X" at 12206.51,2549.64 h60
  text "IMM. TIN/SILVER OR EQUIV" at 11662,2392.64 h60
  text "OTHER" at 13093.46,2392.64 h60
  text "ARRAY/PANEL:" at 11332.46,2213.64 h60
  text "CUT AND TRIM PER MECH LAYER 1" at 12393.46,2209.35 h60
  text "N.C. ROUTE" at 12393.46,2057.64 h60
  text "X" at 13072.46,2057.64 h60
  text "V. SCORE" at 13259.46,2057.64 h60
  text "CERTIFICATION:" at 11332.46,1920.64 h60
  text "MATERIALS AND WORKMANSHIP FOR ALL PCBS" at 12057.46,1920.64 h60
  text "TO MEET OR EXCEED THE REQUIREMENTS OF:" at 12057.46,1822.64 h60
  text "X" at 11683.96,1686.13 h60
  text "ANSI IPC-A-600F CLASS ->" at 11822.96,1686.13 h60
  text "X" at 13462.02,1686.13 h60
  text "2" at 13580.96,1686.14 h60
  text "1" at 13265.96,1684.64 h60
  text "3" at 13934.96,1684.64 h60
  text "X" at 11686.02,1526.64 h60
  text "UL 94V-0" at 11822.96,1526.64 h60
  text "X" at 12498.02,1526.64 h60
  text "RoHS" at 12634.96,1526.64 h60
  text "OTHER" at 13279.36,1526.64 h60
  text "PER ORDER" at 13676.42,1526.64 h60
  text "ADDITIONAL REQUIREMENTS:" at 11332.46,1385.64 h60
  text "MICROSECTION:" at 11407.23,1270.64 h60
  text "YES" at 12312.96,1270.64 h60
  text "REQUIRED" at 13174.46,1114.49 h60
  text "BARE BOARD ELEC. TEST:" at 11407.23,1111.64 h60
  text "NONE" at 12712.96,1111.64 h60
  text "X" at 13047.46,1111.64 h60
  text "PER ORDER" at 13766.46,1111.64 h60
  text "MANUFACTURER'S UL:" at 11407.23,954.64 h60
  text "RAIL" at 12572.96,950.35 h60
  text "METAL" at 13064.77,950.35 h60
  text "X" at 13440,950 h60
  text "SILK" at 13576.46,950.35 h60
  text ".Layer_Name" at 577,-858.49 h60
M11 Gerber Information:
  lines w10: -292,-930.17 6308,-930.17 ; -292,-726.83 6310,-726.83 ; -292,-523.5 -292,-1133.5 3713,-1133.5 6310,-1133.5 6310,-523.5 -291.5,-523.5 -291.5,-1133.5 1284,-1133.5 ; 2173,-1133.5 2173,-523.5 ; 3440,-726.83 3440,-523.5 ; 4280,-726.83 4280,-523.5 ; 4902,-1140 4902,-937.17
  text "ALL ARTWORK VIEWED FROM TOP SIDE" at -228.5,-655.67 h60
  text "BOARD #:" at 2248,-655.67 h60
  text ".PRJ_Number" at 2793.5,-655.67 h60
  text "REV:" at 3638,-655.67 h60
  text ".PCB_Rev" at 3929.5,-655.67 h60
  text "SVN REV:" at 4476,-655.67 h60
  text ".VersionControl_RevNumber" at 4982,-655.67 h60
  text "LAYER NAME =" at -228.5,-858.49 h60
  text "PLOT NAME =" at -228.5,-1064.34 h60
  text ".plot_File_Name" at 577,-1064.34 h60
  text "GENERATED    :" at 2250,-1064.34 h60
  text ".Print_Date" at 3119.5,-1064.34 h60
  text ".Print_Time" at 3848.5,-1064.34 h60
  text "TEXAS INSTRUMENTS" at 5113,-1064.34 h60
M12 Stackup:
  drawing of 191 lines, arcs and shapes, not listed
  text "Layer" at 9790.34,7830 h60
  text "Name" at 10200.26,7830 h60
  text "Material" at 11130,7830 h60
  text "Thickness" at 11989.77,7830 h60
  text "Constant" at 12639.6,7830 h60
  text "Board Layer Stack" at 13209.46,7830 h60
  text "1" at 9790.34,7710 h60
  text "Top Overlay" at 10200.26,7710 h60
  text "2" at 9790.34,7590 h60
  text "Top Solder" at 10200.26,7590 h60
  text "Solder Resist" at 11130,7590 h60
  text "0.40mil" at 11989.77,7590 h60
  text "3.5" at 12639.6,7590 h60
  text "3" at 9790.34,7470 h60
  text "Top Layer" at 10200.26,7470 h60
  text "Copper" at 11130,7470 h60
  text "1.40mil" at 11989.77,7470 h60
  text "4" at 9790.34,7350 h60
  text "Dielectric1" at 10200.26,7350 h60
  text "FR-4" at 11130,7350 h60
  text "59.20mil" at 11989.77,7350 h60
  text "4.8" at 12639.6,7350 h60
  text "5" at 9790.34,7230 h60
  text "Bottom Layer" at 10200.26,7230 h60
  text "Copper" at 11130,7230 h60
  text "1.40mil" at 11989.77,7230 h60
  text "6" at 9790.34,7110 h60
  text "Bottom Solder" at 10200.26,7110 h60
  text "Solder Resist" at 11130,7110 h60
  text "0.40mil" at 11989.77,7110 h60
  text "3.5" at 12639.6,7110 h60
  text "7" at 9790.34,6990 h60
  text "Bottom Overlay" at 10200.26,6990 h60
  text ".Layer_Name" at 577,-858.49 h60
M13 Component Bodies Top:
  text ".Layer_Name" at 577,-858.49 h60
M14 Component Bodies Bottom:
  text ".Layer_Name" at 577,-858.49 h60
M15 Courtyards Top:
  text ".Layer_Name" at 577,-858.49 h60
M16 Courtyards Bottom:
  text ".Layer_Name" at 577,-858.49 h60
Drill Drawing:
  circle w1: c5677.9,3258.91 r20.77
  lines w1: 5657.13,2988.9 5698.67,2988.9 5698.67,3030.44 5657.13,3030.44 5657.13,2988.9 ; 5657.13,3155.06 5698.67,3155.06 5677.9,3113.52 5657.13,3155.06
  lines w12: 5600,2951.51 7629.11,2951.51 ; 5600,3325.38 7629.11,3325.38 ; 5948.13,2826.89 5948.13,3450 ; 6290.32,2826.89 6290.32,3450 ; 6937.06,2826.89 6937.06,3450 ; 7206.38,2826.89 7206.38,3450 ; 5600,2826.89 7629.11,2826.89 7629.11,3450 5600,3450 5600,2826.89
  text "Symbol" at 5674.77,3362.76 h72
  text "Quantity" at 5985.52,3362.76 h72
  text "Finished Hole Size" at 6327.7,3362.76 h72
  text "Plated" at 6974.45,3362.76 h72
  text "Hole Type" at 7243.77,3362.76 h72
  text "2" at 5985.52,3238.14 h60
  text "40.16mil (1.020mm)" at 6327.7,3238.14 h60
  text "NPTH" at 6974.45,3238.14 h60
  text "Round" at 7243.77,3238.14 h60
  text "577" at 5985.52,3113.52 h60
  text "10.00mil (0.254mm)" at 6327.7,3113.52 h60
  text "PTH" at 6974.45,3113.52 h60
  text "Round" at 7243.77,3113.52 h60
  text "4" at 5985.52,2988.9 h60
  text "125.98mil (3.200mm)" at 6327.7,2988.9 h60
  text "PTH" at 6974.45,2988.9 h60
  text "Round" at 7243.77,2988.9 h60
  text "583 Total" at 5985.52,2864.27 h60
  text ".Layer_Name" at 577,-858.49 h60

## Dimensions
0,0 to 4950,0 on M2 Board Dimensions
0,0 to 0,3450 on M2 Board Dimensions
0,-400 to 1000,-400 on M2 Board Dimensions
